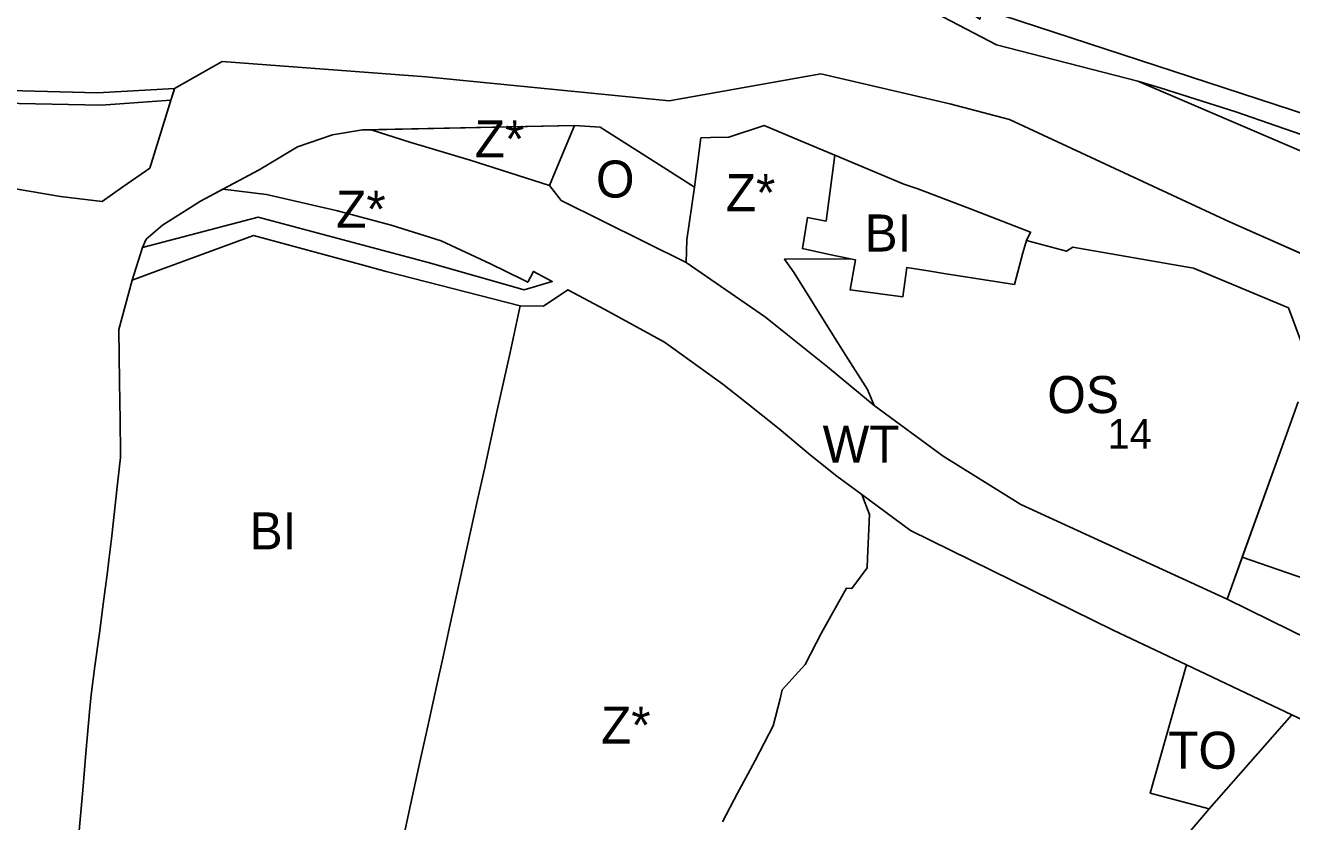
# Model space of a CAD drawing. Extents: x -521621 to -516769, y -1190068 to -1185078.
# Drawn here: x -518947.5 to -518605.8, y -1187385.7 to -1187170.7 of the extents above; entities that cross this region are included whole.
import ezdxf

# ---------------------------------------------------------------- set-up
doc = ezdxf.new("R2010")
doc.units = 0
for name, color, linetype in [('bydleni_s', 7, 'Continuous'), ('fpl_id', 7, 'Continuous'), ('s_zelen_s', 7, 'Continuous'), ('v_infrastr_n', 7, 'Continuous'), ('v_infrastr_s', 7, 'Continuous'), ('voda_s', 7, 'Continuous')]:
    doc.layers.add(name, color=color, linetype=linetype)

msp = doc.modelspace()

# ---------------------------------------------------------------- linework, layer by layer
at = {"layer": 'bydleni_s'}
for p, q in [((-518922.28, -1187252.79), (-518922.11, -1187266.97)), ((-518922.11, -1187266.97), (-518921.98, -1187277.41)), ((-518921.98, -1187277.41), (-518921.87, -1187286.16)), ((-518922.65, -1187294.44), (-518924.33, -1187309.32)), ((-518925.33, -1187318.25), (-518926.51, -1187326.98)), ((-518926.51, -1187326.98), (-518927.56, -1187334.8)), ((-518927.56, -1187334.8), (-518928.76, -1187343.71)), ((-518930.11, -1187354.98), (-518931.18, -1187367.13)), ((-518931.18, -1187367.13), (-518932.05, -1187377.16)), ((-518932.05, -1187377.16), (-518932.92, -1187387.05))]:
    msp.add_line(p, q, dxfattribs=at)
for points in [[(-518724.52, -1187145.17), (-518713.71, -1187152.65), (-518704.01, -1187159.37), (-518689.97, -1187169.09), (-518689.21, -1187166.31), (-518679.09, -1187169.6), (-518578.03, -1187202.6)], [(-518723.56, -1187233.99), (-518724.88, -1187233.78), (-518731.02, -1187232.46), (-518737.86, -1187230.98), (-518736.47, -1187222.64), (-518731.46, -1187223.57), (-518729.06, -1187205.8), (-518710.51, -1187213.58)], [(-518710.51, -1187213.58), (-518706.73, -1187214.89), (-518692.77, -1187220.22), (-518676.25, -1187226.54), (-518677.41, -1187228.78), (-518678.32, -1187232.13)], [(-518856.02, -1187235.56), (-518885.98, -1187227.43), (-518905.33, -1187234.56)], [(-518905.33, -1187234.56), (-518911.7, -1187236.91), (-518918.73, -1187239.5), (-518922.28, -1187252.79)], [(-518709.7, -1187236.14), (-518710.78, -1187244.02), (-518724.98, -1187242.17), (-518723.56, -1187233.99)], [(-518678.32, -1187232.13), (-518680.63, -1187240.65), (-518699.71, -1187237.69), (-518703.41, -1187237.11), (-518709.7, -1187236.14)], [(-518816.75, -1187259), (-518813.98, -1187246.41), (-518850.17, -1187237.15), (-518856.02, -1187235.56)], [(-518820.27, -1187275.04), (-518816.75, -1187259)], [(-518607.2, -1187318.4), (-518619.16, -1187314.3), (-518607.59, -1187282.13), (-518604.06, -1187272.32)], [(-518823.67, -1187290.51), (-518820.27, -1187275.04)], [(-518921.87, -1187286.16), (-518921.86, -1187287.38), (-518922.65, -1187294.44)], [(-518825.49, -1187298.79), (-518823.67, -1187290.51)], [(-518827.48, -1187307.82), (-518825.49, -1187298.79)], [(-518924.33, -1187309.32), (-518924.97, -1187315.06), (-518925.33, -1187318.25)], [(-518831.24, -1187324.94), (-518827.48, -1187307.82)], [(-518590.7, -1187324.08), (-518607.2, -1187318.4)], [(-518833.04, -1187333.14), (-518831.24, -1187324.94)], [(-518834.71, -1187340.76), (-518833.04, -1187333.14)], [(-518836.57, -1187349.21), (-518834.71, -1187340.76)], [(-518928.76, -1187343.71), (-518929.8, -1187351.43), (-518930.11, -1187354.98)], [(-518838.55, -1187358.22), (-518836.57, -1187349.21)], [(-518841.31, -1187370.79), (-518838.55, -1187358.22)], [(-518843.58, -1187381.09), (-518841.31, -1187370.79)], [(-518845.88, -1187391.58), (-518843.58, -1187381.09)]]:
    msp.add_lwpolyline(points, dxfattribs=at)
at = {"layer": 's_zelen_s'}
for points in [[(-519119.53, -1187185.92), (-519058.07, -1187187.23), (-519022.79, -1187186.43), (-518928.1, -1187188.93), (-518907.27, -1187187.83), (-518907.56, -1187188.77), (-518907.91, -1187189.9), (-518908.24, -1187190.95), (-518927.11, -1187192.31), (-518980.23, -1187191.22), (-519020.8, -1187190.92), (-519084.08, -1187192.31), (-519109.21, -1187192.12), (-519122.7, -1187191.89)], [(-518605.3, -1187199.52), (-518609.99, -1187197.89), (-518620.86, -1187194.11), (-518620.86, -1187194.11), (-518633.61, -1187190.05), (-518641.27, -1187187.6), (-518647.32, -1187185.84), (-518559.98, -1187223.23)], [(-518854.24, -1187198.94), (-518799.33, -1187197.8)], [(-518799.33, -1187197.8), (-518804.39, -1187209.84), (-518806.11, -1187213.94), (-518827.53, -1187207.1), (-518843.77, -1187202.27), (-518854.24, -1187198.94)], [(-518762.61, -1187201.02), (-518765.25, -1187201.09)], [(-518738.34, -1187201.91), (-518748.12, -1187197.81), (-518757.67, -1187200.89), (-518762.61, -1187201.02)], [(-518765.25, -1187201.09), (-518766.94, -1187214.44)], [(-518724.88, -1187233.78), (-518731.02, -1187232.46), (-518737.86, -1187230.98), (-518736.47, -1187222.64), (-518731.46, -1187223.57), (-518729.06, -1187205.8), (-518738.34, -1187201.91)], [(-518766.94, -1187214.44), (-518768.99, -1187228.62), (-518769.23, -1187234.77), (-518747.8, -1187249.52), (-518741.87, -1187254.25), (-518731.06, -1187262.88), (-518718.5, -1187273.35)], [(-518894.28, -1187214.98), (-518882.5, -1187216.39), (-518863.29, -1187220.79), (-518848.78, -1187224.65), (-518835.36, -1187228.89), (-518822.01, -1187235.07), (-518813.41, -1187239.36), (-518811.98, -1187240.08), (-518810.43, -1187237.15), (-518805.36, -1187239.85), (-518812.9, -1187242.09), (-518838.83, -1187234.76), (-518884.74, -1187222.49), (-518915.95, -1187230.71)], [(-518914.95, -1187228.43), (-518910.5, -1187224.71), (-518900.23, -1187218.16), (-518894.28, -1187214.98)], [(-518915.95, -1187230.71), (-518914.95, -1187228.43)], [(-518742.72, -1187233.88), (-518724.88, -1187233.78)], [(-518740.03, -1187237.56), (-518742.72, -1187233.88)], [(-518729.6, -1187254.26), (-518740.03, -1187237.56)], [(-518772.83, -1187257.85), (-518775.02, -1187256.29), (-518791.14, -1187247.41), (-518801.12, -1187242.1), (-518807.73, -1187246.49), (-518813.98, -1187246.41)], [(-518813.98, -1187246.41), (-518816.75, -1187259)], [(-518726.08, -1187259.89), (-518729.6, -1187254.26)], [(-518816.75, -1187259), (-518820.27, -1187275.04)], [(-518759.4, -1187385.65), (-518755.32, -1187377.99), (-518752.56, -1187372.81), (-518750.6, -1187369.14), (-518745.72, -1187359.77), (-518743.84, -1187352.49), (-518743.26, -1187350.08), (-518737.13, -1187343.25), (-518732.69, -1187334.72), (-518725.98, -1187322.61), (-518724.46, -1187322.76), (-518720.4, -1187317.18), (-518720.28, -1187314.5), (-518719.77, -1187302.74), (-518721.82, -1187297.37), (-518728.57, -1187292.4), (-518735.66, -1187286.77), (-518744.15, -1187279.67), (-518752.9, -1187272.66), (-518759.28, -1187267.55), (-518772.83, -1187257.85)], [(-518720.29, -1187269.06), (-518726.08, -1187259.89)], [(-518718.5, -1187273.35), (-518720.29, -1187269.06)], [(-518820.27, -1187275.04), (-518823.67, -1187290.51)], [(-518823.67, -1187290.51), (-518825.49, -1187298.79)], [(-518825.49, -1187298.79), (-518827.48, -1187307.82)], [(-518827.48, -1187307.82), (-518831.24, -1187324.94)], [(-518831.24, -1187324.94), (-518833.04, -1187333.14)], [(-518833.04, -1187333.14), (-518834.71, -1187340.76)], [(-518834.71, -1187340.76), (-518836.57, -1187349.21)], [(-518836.57, -1187349.21), (-518838.55, -1187358.22)], [(-518838.55, -1187358.22), (-518841.31, -1187370.79), (-518843.58, -1187381.09), (-518845.88, -1187391.58)]]:
    msp.add_lwpolyline(points, dxfattribs=at)
at = {"layer": 'v_infrastr_n'}
msp.add_lwpolyline([(-518604.06, -1187272.32), (-518607.59, -1187282.13), (-518623.21, -1187325.56), (-518678.91, -1187300.04), (-518699.82, -1187287), (-518718.5, -1187273.35), (-518720.29, -1187269.06), (-518726.08, -1187259.89), (-518729.6, -1187254.26), (-518740.03, -1187237.56), (-518742.72, -1187233.88), (-518724.88, -1187233.78), (-518723.56, -1187233.99), (-518724.18, -1187237.56), (-518724.98, -1187242.17), (-518710.78, -1187244.02), (-518709.7, -1187236.14), (-518703.41, -1187237.11), (-518699.71, -1187237.69), (-518680.63, -1187240.65), (-518678.32, -1187232.13), (-518677.41, -1187228.78), (-518666.6, -1187231.71), (-518664.87, -1187230.59), (-518632.31, -1187236.3), (-518606.69, -1187246.95), (-518598.4, -1187269.16)], dxfattribs=at)
at = {"layer": 'v_infrastr_s'}
for p, q in [((-518714.03, -1187161.03), (-518685.48, -1187176.02)), ((-518685.48, -1187176.02), (-518647.32, -1187185.84)), ((-518894.42, -1187180.55), (-518907.27, -1187187.83)), ((-518839.4, -1187184.64), (-518894.42, -1187180.55)), ((-518732.85, -1187183.84), (-518773.82, -1187191.12)), ((-518698.07, -1187191.92), (-518732.85, -1187183.84)), ((-518773.82, -1187191.12), (-518839.4, -1187184.64)), ((-518681.92, -1187196.2), (-518698.07, -1187191.92)), ((-518622.62, -1187223.81), (-518681.92, -1187196.2)), ((-518799.33, -1187197.8), (-518792.45, -1187198.2)), ((-518765.25, -1187201.09), (-518762.61, -1187201.02)), ((-518762.61, -1187201.02), (-518757.67, -1187200.89)), ((-518757.67, -1187200.89), (-518748.12, -1187197.81)), ((-518541.39, -1187259.69), (-518622.62, -1187223.81)), ((-518922.28, -1187252.79), (-518918.73, -1187239.5)), ((-518924.97, -1187315.06), (-518924.33, -1187309.32)), ((-518724.46, -1187322.76), (-518720.4, -1187317.18)), ((-518745.72, -1187359.77), (-518743.84, -1187352.49))]:
    msp.add_line(p, q, dxfattribs=at)
for points in [[(-518714.03, -1187161.03), (-518685.48, -1187176.02)], [(-518448.05, -1187243.78), (-518451.33, -1187242.83), (-518454.9, -1187241.8), (-518460.05, -1187240.32), (-518463.62, -1187239.29), (-518470.62, -1187237.28), (-518472.37, -1187236.78), (-518473.22, -1187236.53), (-518534.43, -1187216.02), (-518545.72, -1187212.65), (-518576.26, -1187203.11), (-518578.03, -1187202.6), (-518679.09, -1187169.6)], [(-518685.48, -1187176.02), (-518647.32, -1187185.84)], [(-518894.42, -1187180.55), (-518907.27, -1187187.83)], [(-518839.4, -1187184.64), (-518894.42, -1187180.55)], [(-518732.85, -1187183.84), (-518773.82, -1187191.12)], [(-518698.07, -1187191.92), (-518732.85, -1187183.84)], [(-518928.1, -1187188.93), (-519022.79, -1187186.43)], [(-518773.82, -1187191.12), (-518839.4, -1187184.64)], [(-518647.32, -1187185.84), (-518641.27, -1187187.6), (-518633.61, -1187190.05), (-518620.86, -1187194.11), (-518609.99, -1187197.89), (-518605.3, -1187199.52), (-518589.47, -1187205.01), (-518579.72, -1187208.26), (-518563.36, -1187213.71), (-518558.55, -1187215.31), (-518547.62, -1187218.83), (-518536.36, -1187222.46), (-518520.13, -1187227.68), (-518507.84, -1187231.68), (-518497.26, -1187235.12), (-518485.67, -1187238.69), (-518474.73, -1187242.06), (-518465.16, -1187245.01), (-518456.53, -1187247.72)], [(-518647.32, -1187185.84), (-518559.98, -1187223.23)], [(-518907.27, -1187187.83), (-518928.1, -1187188.93)], [(-518907.27, -1187187.83), (-518913.92, -1187209.27)], [(-518681.92, -1187196.2), (-518698.07, -1187191.92)], [(-518622.62, -1187223.81), (-518681.92, -1187196.2)], [(-518914.95, -1187228.43), (-518910.5, -1187224.71), (-518900.23, -1187218.16), (-518884.43, -1187209.71), (-518874.08, -1187203.57), (-518864.64, -1187200.32), (-518856.58, -1187198.99)], [(-518856.58, -1187198.99), (-518799.33, -1187197.8)], [(-518792.45, -1187198.2), (-518774.46, -1187209.66), (-518766.94, -1187214.44)], [(-518748.12, -1187197.81), (-518738.34, -1187201.91), (-518729.06, -1187205.8), (-518710.51, -1187213.58)], [(-518766.94, -1187214.44), (-518765.25, -1187201.09)], [(-518913.92, -1187209.27), (-518921.22, -1187214.35)], [(-518926.85, -1187218.28), (-518938.06, -1187216.93), (-518954.5, -1187214.16), (-518953.8, -1187221.45), (-518953.96, -1187225.65)], [(-518921.22, -1187214.35), (-518926.85, -1187218.28)], [(-518710.51, -1187213.58), (-518706.73, -1187214.89)], [(-518706.73, -1187214.89), (-518692.77, -1187220.22), (-518676.25, -1187226.54), (-518677.41, -1187228.78), (-518666.6, -1187231.71), (-518664.87, -1187230.59), (-518632.31, -1187236.3), (-518606.69, -1187246.95), (-518598.4, -1187269.16)], [(-518541.39, -1187259.69), (-518622.62, -1187223.81)], [(-518918.73, -1187239.5), (-518915.95, -1187230.71), (-518914.95, -1187228.43)], [(-518924.33, -1187309.32), (-518922.65, -1187294.44), (-518921.86, -1187287.38), (-518921.87, -1187286.16), (-518921.98, -1187277.41), (-518922.11, -1187266.97), (-518922.28, -1187252.79)], [(-518719.77, -1187302.74), (-518721.82, -1187297.37)], [(-518721.82, -1187297.37), (-518708.66, -1187307.06), (-518653.95, -1187333.99), (-518634.2, -1187343.35), (-518644.03, -1187377.98), (-518628.1, -1187382.14), (-518641.6, -1187398.11), (-518647.62, -1187418.94), (-518656.03, -1187447.42), (-518696.16, -1187451.2), (-518696.32, -1187449.96), (-518696.85, -1187445.8), (-518710.58, -1187447.02)], [(-518720.28, -1187314.5), (-518719.77, -1187302.74)], [(-518926.64, -1187424.96), (-518927.67, -1187409), (-518927.88, -1187405.67), (-518932.89, -1187405.29), (-518933.12, -1187389.31), (-518932.92, -1187387.05), (-518932.05, -1187377.16), (-518931.18, -1187367.13), (-518930.11, -1187354.98), (-518929.8, -1187351.43), (-518928.76, -1187343.71), (-518927.56, -1187334.8), (-518926.51, -1187326.98), (-518925.33, -1187318.25), (-518924.97, -1187315.06)], [(-518720.4, -1187317.18), (-518720.28, -1187314.5)], [(-518590.7, -1187324.08), (-518607.2, -1187318.4), (-518619.16, -1187314.3), (-518623.21, -1187325.56), (-518611.68, -1187331.23), (-518596.14, -1187338.88)], [(-518732.69, -1187334.72), (-518725.98, -1187322.61)], [(-518725.98, -1187322.61), (-518724.46, -1187322.76)], [(-518737.13, -1187343.25), (-518732.69, -1187334.72)], [(-518743.26, -1187350.08), (-518737.13, -1187343.25)], [(-518743.84, -1187352.49), (-518743.26, -1187350.08)], [(-518597.94, -1187360.53), (-518605.81, -1187356.8), (-518628.1, -1187382.14), (-518641.6, -1187398.11), (-518647.62, -1187418.94), (-518656.03, -1187447.42)], [(-518750.6, -1187369.14), (-518745.72, -1187359.77)], [(-518752.56, -1187372.81), (-518750.6, -1187369.14)], [(-518755.32, -1187377.99), (-518752.56, -1187372.81)], [(-518759.4, -1187385.65), (-518755.32, -1187377.99)]]:
    msp.add_lwpolyline(points, dxfattribs=at)
for points in [[(-518774.46, -1187209.66), (-518766.94, -1187214.44), (-518768.99, -1187228.62), (-518769.23, -1187234.77), (-518802.92, -1187218.03), (-518804.19, -1187216.4), (-518806.11, -1187213.94), (-518804.39, -1187209.84), (-518799.33, -1187197.8), (-518792.45, -1187198.2)], [(-518634.2, -1187343.35), (-518644.03, -1187377.98), (-518628.1, -1187382.14), (-518605.81, -1187356.8)]]:
    msp.add_lwpolyline(points, close=True, dxfattribs=at)
at = {"layer": 'voda_s'}
for points in [[(-519582.24, -1187178.82), (-519519.49, -1187187.61), (-519366.03, -1187190.07), (-519365.76, -1187190.07), (-519260.22, -1187189.55), (-519122.7, -1187191.89), (-519109.21, -1187192.12), (-519084.08, -1187192.31), (-519020.8, -1187190.92), (-518980.23, -1187191.22), (-518927.11, -1187192.31), (-518908.24, -1187190.95)], [(-518908.24, -1187190.95), (-518913.92, -1187209.27)], [(-518874.08, -1187203.57), (-518864.64, -1187200.32), (-518856.58, -1187198.99), (-518854.24, -1187198.94), (-518843.77, -1187202.27), (-518827.53, -1187207.1), (-518806.11, -1187213.94), (-518804.19, -1187216.4), (-518802.92, -1187218.03), (-518769.23, -1187234.77), (-518747.8, -1187249.52), (-518741.87, -1187254.25), (-518731.06, -1187262.88), (-518718.5, -1187273.35), (-518699.82, -1187287), (-518678.91, -1187300.04), (-518623.21, -1187325.56), (-518611.68, -1187331.23), (-518596.14, -1187338.88)], [(-518884.43, -1187209.71), (-518874.08, -1187203.57)], [(-518913.92, -1187209.27), (-518921.22, -1187214.35), (-518926.85, -1187218.28)], [(-518805.36, -1187239.85), (-518810.43, -1187237.15), (-518811.98, -1187240.08), (-518813.41, -1187239.36), (-518822.01, -1187235.07), (-518835.36, -1187228.89), (-518848.78, -1187224.65), (-518863.29, -1187220.79), (-518882.5, -1187216.39), (-518894.28, -1187214.98), (-518884.43, -1187209.71)], [(-518938.06, -1187216.93), (-518954.5, -1187214.16)], [(-518926.85, -1187218.28), (-518938.06, -1187216.93)], [(-518915.95, -1187230.71), (-518884.74, -1187222.49), (-518838.83, -1187234.76), (-518812.9, -1187242.09), (-518805.36, -1187239.85)], [(-518801.12, -1187242.1), (-518807.73, -1187246.49), (-518813.98, -1187246.41), (-518850.17, -1187237.15), (-518856.02, -1187235.56), (-518885.98, -1187227.43), (-518905.33, -1187234.56), (-518911.7, -1187236.91), (-518918.73, -1187239.5)], [(-518918.73, -1187239.5), (-518915.95, -1187230.71)], [(-518605.81, -1187356.8), (-518634.2, -1187343.35), (-518653.95, -1187333.99), (-518708.66, -1187307.06), (-518721.82, -1187297.37), (-518728.57, -1187292.4), (-518735.66, -1187286.77), (-518744.15, -1187279.67), (-518752.9, -1187272.66), (-518759.28, -1187267.55), (-518775.02, -1187256.29), (-518791.14, -1187247.41), (-518801.12, -1187242.1)], [(-518597.94, -1187360.53), (-518605.81, -1187356.8)]]:
    msp.add_lwpolyline(points, dxfattribs=at)

# ---------------------------------------------------------------- texts
at = {"layer": 'bydleni_s'}
for p in [(-518721.07, -1187231.79), (-518887.03, -1187312.17)]:
    msp.add_text('BI', height=10, dxfattribs=at).set_placement(p)
at = {"layer": 'fpl_id'}
msp.add_text('14', height=8, dxfattribs=at).set_placement((-518655.48, -1187284.99))
at = {"layer": 's_zelen_s'}
for p in [(-518826.27, -1187206.4), (-518758.52, -1187220.9), (-518863.67, -1187225.34), (-518792.19, -1187364.58)]:
    msp.add_text('Z*', height=10, dxfattribs=at).set_placement(p)
at = {"layer": 'v_infrastr_n'}
msp.add_text('OS', height=10, dxfattribs=at).set_placement((-518671.75, -1187275.39))
at = {"layer": 'v_infrastr_s'}
for s, p in [('O', (-518793.55, -1187217.23)), ('TO', (-518639.14, -1187371.37))]:
    msp.add_text(s, height=10, dxfattribs=at).set_placement(p)
at = {"layer": 'voda_s'}
msp.add_text('WT', height=10, dxfattribs=at).set_placement((-518732.4, -1187288.74))

doc.saveas('drawing.dxf')
